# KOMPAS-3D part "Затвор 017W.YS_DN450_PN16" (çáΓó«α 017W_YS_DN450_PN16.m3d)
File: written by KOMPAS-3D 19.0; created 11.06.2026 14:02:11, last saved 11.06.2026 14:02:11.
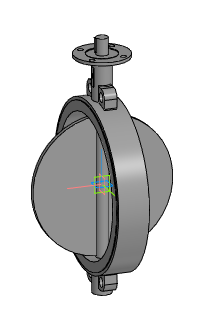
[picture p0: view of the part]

Document properties: Автор: Евгений; Полное имя файла: Z:\3.Личные\kachalov\001_3d для проектировщиков\x.x Тип 017W.Y(S) Затвор дисковый поворотный межфланцевый\_stp_Затвор 017W.YS_DN32-DN1200\Затвор 017W_YS_DN450_PN16.m3d

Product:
- Part/product: Затвор 017W.YS_DN450_PN16

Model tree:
1. Операция без истории:1  (labels: Затвор 017W.YS_DN450_PN16)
